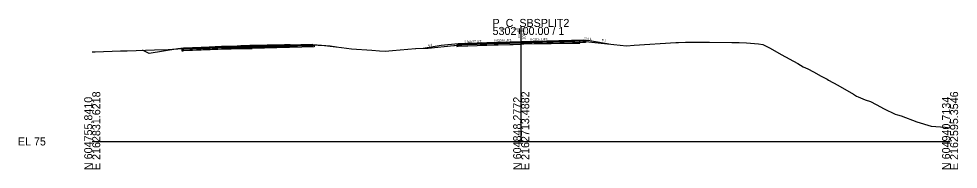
# Model space of a CAD drawing. Extents: x -26 to 1303, y -10 to 12033.
# Drawn here: x -25.7 to 302.8, y 11490.3 to 11542.8 of the extents above; entities that cross this region are included whole.
import ezdxf

# ---------------------------------------------------------------- set-up
doc = ezdxf.new("R2010")
doc.units = 0
for name, color, linetype in [('RD_GPK_XS_Cell', 7, 'Continuous'), ('RD_XS_Base', 7, 'Continuous'), ('RD_XS_ExGround', 7, 'Continuous'), ('RD_XS_ExPaveRet', 7, 'Continuous'), ('RD_XS_Greenside', 7, 'Continuous'), ('RD_XS_Pave', 7, 'Continuous'), ('RD_XS_PaveOvlay_CP', 7, 'Continuous'), ('RD_XS_TieSlope', 7, 'Continuous'), ('RD_XS_TX_Elev_EX', 7, 'Continuous'), ('RD_XS_TX_Elev_PR', 7, 'Continuous'), ('RD_XS_TX_ShdSlope', 7, 'Continuous'), ('RD_XS_TX_Slope', 7, 'Continuous')]:
    doc.layers.add(name, color=color, linetype=linetype)

msp = doc.modelspace()

# ---------------------------------------------------------------- linework, layer by layer
at = {"layer": 'RD_GPK_XS_Cell'}
for p, q in [((150, 11500), (150, 11540)), ((0, 11500), (150, 11500)), ((150, 11500), (300, 11500))]:
    msp.add_line(p, q, dxfattribs=at)
at = {"layer": 'RD_XS_Base'}
for p, q in [((150, 11534.47), (172, 11535.09)), ((162, 11534.81), (162, 11534.81)), ((162, 11534.81), (162, 11534.81)), ((172, 11535.09), (172, 11535.09)), ((172.5, 11535.1), (172.5, 11534.6)), ((172.5, 11535.07), (172.5, 11535.07)), ((31.77, 11532.21), (31.38, 11532.2)), ((31.38, 11532.2), (31.38, 11532.09)), ((31.38, 11532.09), (31.38, 11531.7)), ((31.38, 11531.7), (31.77, 11531.71)), ((31.88, 11532.22), (31.77, 11532.21)), ((31.77, 11531.71), (31.88, 11531.72)), ((41.26, 11532.59), (31.88, 11532.22)), ((31.88, 11531.72), (41.26, 11532.09)), ((43.88, 11532.7), (41.26, 11532.59)), ((41.26, 11532.09), (43.88, 11532.2)), ((53.33, 11532.94), (43.88, 11532.7)), ((43.88, 11532.2), (53.33, 11532.44)), ((55.88, 11533.01), (53.33, 11532.94)), ((53.33, 11532.44), (55.88, 11532.51)), ((55.88, 11533.01), (77.66, 11533.58)), ((55.88, 11532.51), (55.88, 11533.17)), ((55.88, 11533.17), (55.88, 11533.17)), ((55.88, 11533.17), (55.88, 11533.17)), ((55.88, 11533.17), (55.88, 11533.01)), ((77.66, 11533.08), (55.88, 11532.51)), ((55.88, 11533.01), (55.88, 11533.01)), ((55.88, 11532.51), (55.88, 11533.01)), ((55.88, 11533.01), (55.88, 11533.01)), ((55.88, 11533.01), (55.88, 11533.01)), ((55.88, 11532.51), (55.88, 11532.51)), ((77.16, 11533.56), (77.16, 11533.56)), ((77.66, 11533.58), (77.66, 11533.08)), ((77.66, 11533.54), (77.66, 11533.54)), ((128, 11533.73), (127.5, 11533.71)), ((127.5, 11533.71), (127.5, 11533.71)), ((127.5, 11533.71), (127.5, 11533.21)), ((127.5, 11533.21), (128, 11533.23)), ((138, 11534.13), (128, 11533.73)), ((128, 11533.73), (128, 11533.73)), ((128, 11533.23), (138, 11533.63)), ((128, 11533.23), (128, 11533.23)), ((136, 11534.05), (136, 11534.05)), ((136, 11533.55), (136, 11533.55)), ((150, 11534.47), (138, 11534.13)), ((138, 11533.63), (150, 11533.97)), ((150, 11533.97), (150, 11534.63)), ((150, 11534.63), (150, 11534.63)), ((150, 11534.63), (150, 11534.63)), ((150, 11534.63), (150, 11534.47)), ((172.5, 11534.6), (150, 11533.97)), ((150, 11534.47), (150, 11534.47)), ((150, 11533.97), (150, 11534.47)), ((150, 11534.47), (150, 11534.47)), ((150, 11534.47), (150, 11534.47)), ((150, 11533.97), (150, 11533.97)), ((162, 11534.31), (162, 11534.31)), ((162, 11534.31), (162, 11534.31))]:
    msp.add_line(p, q, dxfattribs=at)
at = {"layer": 'RD_XS_ExGround'}
msp.add_lwpolyline([(0, 11531.28), (1.01, 11531.32), (9.89, 11531.62), (12.26, 11531.71), (21.79, 11532.01), (26.54, 11532.17), (28.07, 11532.25), (31.76, 11532.49), (38.63, 11532.84), (52.16, 11533.41), (53.78, 11533.41), (53.84, 11533.41), (53.86, 11533.41), (54.04, 11533.42), (55.73, 11533.5), (55.89, 11533.51), (58.41, 11533.56), (67.19, 11533.75), (69.18, 11533.8), (70.58, 11533.79), (71.12, 11533.8), (74.04, 11533.76), (78.95, 11533.67), (81.21, 11533.5), (87.22, 11532.82), (90.64, 11532.4), (97.76, 11531.86), (100.46, 11531.68), (102.42, 11531.5), (104.98, 11531.77), (113, 11532.5), (113.12, 11532.5), (117.48, 11532.54), (126.46, 11533.49), (126.56, 11533.5), (126.69, 11533.51), (135.83, 11534.34), (140.5, 11534.45), (147.18, 11534.64), (150, 11534.77), (150.9, 11534.85), (170.03, 11535.13), (170.5, 11535.14), (171.62, 11535.02), (175.74, 11534.59), (186.85, 11533.45), (189.51, 11533.63), (204.06, 11534.59), (205.05, 11534.6), (207.48, 11534.64), (210.42, 11534.65), (215.89, 11534.64), (223.71, 11534.62), (226.27, 11534.56), (228.84, 11534.48), (232.94, 11534.05), (234.55, 11533.87), (237.08, 11532.59), (240.98, 11530.33), (246.73, 11527.23), (248.6, 11526.05), (250.23, 11525.39), (252.18, 11524.31), (254.96, 11522.76), (256.97, 11521.8), (257.45, 11521.46), (260.69, 11519.64), (266.18, 11516.49), (267.25, 11515.81), (267.86, 11515.57), (270.32, 11514.55), (272.14, 11513.9), (274.16, 11512.96), (276.98, 11511.39), (280.85, 11509.57), (281.58, 11509.33), (282.91, 11508.9), (288.33, 11506.85), (293.34, 11505.39), (298.25, 11504.97), (300, 11504.77)], dxfattribs=at)
at = {"layer": 'RD_XS_ExPaveRet'}
for points in [[(170.03, 11535.13), (150.9, 11534.85), (150.9, 11534.85), (150, 11534.77), (150, 11534.77), (150, 11534.77), (147.18, 11534.64), (140.5, 11534.45), (140.5, 11534.45), (135.83, 11534.34), (135.83, 11534.34), (135.83, 11534.34), (135.83, 11534.34), (135.83, 11533.59), (135.83, 11533.59), (135.83, 11533.59), (140.5, 11533.7), (140.5, 11533.7), (147.18, 11533.89), (150, 11534.02), (150, 11534.02), (150, 11534.02), (150.9, 11534.1), (150.9, 11534.1), (170.03, 11534.38), (170.03, 11534.38), (170.5, 11534.39), (170.5, 11535.14), (170.5, 11535.14), (170.03, 11535.13), (170.03, 11535.13)], [(170.03, 11535.13), (150.9, 11534.85), (150, 11534.77), (147.18, 11534.64), (140.5, 11534.45), (135.83, 11534.34), (135.83, 11533.59), (140.5, 11533.7), (147.18, 11533.89), (150, 11534.02), (150.9, 11534.1), (170.03, 11534.38), (170.5, 11534.39), (170.5, 11535.14), (170.03, 11535.13)], [(69.18, 11533.8), (69.17, 11533.8), (67.18, 11533.75), (61.2, 11533.62), (56.2, 11533.52), (55.83, 11533.5), (55.08, 11533.46), (54.28, 11533.43), (53.95, 11533.42), (53.84, 11533.41), (53.83, 11533.41), (53.31, 11533.42), (52.66, 11533.4), (51.99, 11533.4), (50.64, 11533.34), (45.21, 11533.12), (38.63, 11532.84), (34.07, 11532.61), (31.76, 11532.49), (31.76, 11532.14), (31.76, 11531.74), (34.07, 11531.86), (38.63, 11532.09), (45.21, 11532.37), (50.64, 11532.59), (51.99, 11532.65), (52.66, 11532.65), (53.31, 11532.67), (53.83, 11532.66), (53.84, 11532.66), (53.95, 11532.67), (54.28, 11532.68), (55.08, 11532.71), (55.83, 11532.75), (56.2, 11532.77), (61.2, 11532.87), (67.18, 11533), (69.17, 11533.05), (69.18, 11533.05), (69.18, 11533.05), (69.18, 11533.45), (69.18, 11533.8), (69.18, 11533.8)], [(69.18, 11533.8), (69.17, 11533.8), (67.18, 11533.75), (61.2, 11533.62), (56.2, 11533.52), (55.83, 11533.5), (55.08, 11533.46), (54.28, 11533.43), (53.95, 11533.42), (53.84, 11533.41), (53.83, 11533.41), (53.31, 11533.42), (52.66, 11533.4), (51.99, 11533.4), (50.64, 11533.34), (45.21, 11533.12), (38.63, 11532.84), (34.07, 11532.61), (31.76, 11532.49), (31.76, 11532.14), (31.76, 11531.74), (34.07, 11531.86), (38.63, 11532.09), (45.21, 11532.37), (50.64, 11532.59), (51.99, 11532.65), (52.66, 11532.65), (53.31, 11532.67), (53.83, 11532.66), (53.84, 11532.66), (53.95, 11532.67), (54.28, 11532.68), (55.08, 11532.71), (55.83, 11532.75), (56.2, 11532.77), (61.2, 11532.87), (67.18, 11533), (69.17, 11533.05), (69.18, 11533.05), (69.18, 11533.05), (69.18, 11533.45), (69.18, 11533.8), (69.18, 11533.8)]]:
    msp.add_lwpolyline(points, dxfattribs=at)
at = {"layer": 'RD_XS_Greenside'}
for p, q in [((174, 11535.24), (181.41, 11534.01)), ((19.88, 11530.71), (17.56, 11531.87)), ((29.88, 11532.38), (19.88, 11530.71)), ((83.16, 11533.4), (85.46, 11533.02)), ((122, 11533.57), (115.71, 11532.52))]:
    msp.add_line(p, q, dxfattribs=at)
at = {"layer": 'RD_XS_Pave'}
for p, q in [((150, 11534.79), (138, 11534.45)), ((172, 11535.4), (150, 11534.79)), ((172, 11535.24), (150, 11534.63)), ((150, 11534.63), (172, 11535.24)), ((150, 11534.47), (172.5, 11535.1)), ((150, 11534.79), (150, 11534.79)), ((162, 11535.12), (162, 11535.12)), ((162, 11535.12), (162, 11535.12)), ((162, 11534.96), (162, 11534.96)), ((162, 11534.96), (162, 11534.96)), ((162, 11534.96), (162, 11534.96)), ((162, 11534.96), (162, 11534.96)), ((162, 11534.81), (162, 11534.81)), ((162, 11534.81), (162, 11534.81)), ((172, 11535.24), (172, 11535.4)), ((172, 11535.4), (172, 11535.4)), ((172, 11535.09), (172, 11535.24)), ((172, 11535.24), (172, 11535.24)), ((41.26, 11532.91), (31.88, 11532.54)), ((31.88, 11532.38), (41.26, 11532.75)), ((41.26, 11532.75), (31.88, 11532.38)), ((31.88, 11532.22), (41.26, 11532.59)), ((31.88, 11532.54), (31.88, 11532.5)), ((31.88, 11532.5), (31.88, 11532.38)), ((31.88, 11532.38), (31.88, 11532.34)), ((31.88, 11532.34), (31.88, 11532.22)), ((43.88, 11533.02), (41.26, 11532.91)), ((41.26, 11532.75), (43.88, 11532.86)), ((43.88, 11532.86), (41.26, 11532.75)), ((41.26, 11532.59), (43.88, 11532.7)), ((53.33, 11533.26), (43.88, 11533.02)), ((43.88, 11532.86), (53.33, 11533.1)), ((53.33, 11533.1), (43.88, 11532.86)), ((43.88, 11532.7), (53.33, 11532.94)), ((55.88, 11533.33), (53.33, 11533.26)), ((53.33, 11533.1), (55.88, 11533.17)), ((55.88, 11533.17), (53.33, 11533.1)), ((53.33, 11532.94), (55.88, 11533.01)), ((77.16, 11533.88), (55.88, 11533.33)), ((77.16, 11533.72), (55.88, 11533.17)), ((55.88, 11533.17), (77.16, 11533.72)), ((55.88, 11533.01), (77.16, 11533.56)), ((55.88, 11533.33), (55.88, 11533.33)), ((55.88, 11533.17), (55.88, 11533.17)), ((55.88, 11533.17), (55.88, 11533.17)), ((55.88, 11533.17), (55.88, 11533.01)), ((55.88, 11533.17), (55.88, 11533.17)), ((55.88, 11533.01), (55.88, 11533.17)), ((55.88, 11533.17), (55.88, 11533.17)), ((55.88, 11533.17), (55.88, 11533.17)), ((55.88, 11533.01), (55.88, 11533.01)), ((55.88, 11533.01), (55.88, 11533.01)), ((77.16, 11533.72), (77.16, 11533.88)), ((77.16, 11533.88), (77.16, 11533.88)), ((77.16, 11533.56), (77.16, 11533.72)), ((77.16, 11533.72), (77.16, 11533.72)), ((138, 11534.45), (128, 11534.05)), ((128, 11533.89), (138, 11534.29)), ((138, 11534.29), (128, 11533.89)), ((128, 11533.73), (138, 11534.13)), ((128, 11534.05), (128, 11534.05)), ((128, 11534.05), (128, 11533.89)), ((128, 11533.89), (128, 11533.89)), ((128, 11533.89), (128, 11533.73)), ((136, 11534.37), (136, 11534.37)), ((136, 11534.21), (136, 11534.21)), ((136, 11534.21), (136, 11534.21)), ((136, 11534.05), (136, 11534.05)), ((138, 11534.29), (150, 11534.63)), ((150, 11534.63), (138, 11534.29)), ((138, 11534.13), (150, 11534.47)), ((150, 11534.63), (150, 11534.63)), ((150, 11534.63), (150, 11534.63)), ((150, 11534.63), (150, 11534.47)), ((150, 11534.63), (150, 11534.63)), ((150, 11534.47), (150, 11534.63)), ((150, 11534.63), (150, 11534.63)), ((150, 11534.63), (150, 11534.63)), ((150, 11534.47), (150, 11534.47)), ((150, 11534.47), (150, 11534.47))]:
    msp.add_line(p, q, dxfattribs=at)
at = {"layer": 'RD_XS_PaveOvlay_CP'}
for p, q in [((150, 11534.79), (138, 11534.45)), ((172, 11535.4), (150, 11534.79)), ((150, 11534.79), (150, 11534.79)), ((162, 11535.12), (162, 11535.12)), ((162, 11535.12), (162, 11535.12)), ((41.26, 11532.91), (31.88, 11532.54)), ((43.88, 11533.02), (41.26, 11532.91)), ((53.33, 11533.26), (43.88, 11533.02)), ((55.88, 11533.33), (53.33, 11533.26)), ((77.16, 11533.88), (55.88, 11533.33)), ((55.88, 11533.33), (55.88, 11533.33)), ((138, 11534.45), (128, 11534.05)), ((136, 11534.37), (136, 11534.37))]:
    msp.add_line(p, q, dxfattribs=at)
at = {"layer": 'RD_XS_TieSlope'}
for p, q in [((172, 11535.4), (174, 11535.24)), ((31.88, 11532.54), (29.88, 11532.38)), ((77.16, 11533.88), (83.16, 11533.4)), ((128, 11534.05), (122, 11533.57))]:
    msp.add_line(p, q, dxfattribs=at)

# ---------------------------------------------------------------- texts
at = {"layer": 'RD_GPK_XS_Cell'}
for s, p in [('P_C_SBSPLIT2', (140, 11540)), ('5302+00.00 / 1', (140, 11537.2)), ('EL 75', (-26, 11498.6))]:
    msp.add_text(s, height=2.8, dxfattribs=at).set_placement(p)
for s, p in [('N 604755.8410', (0, 11490)), ('E 2162831.6218', (2.8, 11490)), ('N 604848.2772', (150, 11490)), ('E 2162713.4882', (152.8, 11490)), ('N 604940.7134', (300, 11490)), ('E 2162595.3546', (302.8, 11490))]:
    msp.add_text(s, height=2.8, rotation=90, dxfattribs=at).set_placement(p)
at = {"layer": 'RD_XS_TX_Elev_EX'}
msp.add_text('109.77', height=0.6, rotation=90, dxfattribs=at).set_placement((149.61, 11536.05))
at = {"layer": 'RD_XS_TX_Elev_PR'}
msp.add_text('109.79', height=1, rotation=90, dxfattribs=at).set_placement((151.45, 11535.52))
at = {"layer": 'RD_XS_TX_ShdSlope'}
msp.add_text('12.5:1', height=0.75, rotation=355.4261, dxfattribs=at).set_placement((171.75, 11535.67))
at = {"layer": 'RD_XS_TX_Slope'}
for s, rotation, p in [('0.040 FT./FT.', 2.2906, (130.15, 11534.42)), ('0.030 FT./FT.', 1.7184, (140.51, 11534.85)), ('0.030 FT./FT.', 1.7184, (153.16, 11535.21)), ('6:1', 350.5358, (178.13, 11535.09)), ('6:1', 9.4623, (117.58, 11533.2))]:
    msp.add_text(s, height=0.75, rotation=rotation, dxfattribs=at).set_placement(p)

doc.saveas('drawing.dxf')
